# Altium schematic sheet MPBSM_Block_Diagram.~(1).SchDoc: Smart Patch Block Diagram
size 431 x 279 mm; Date: Not shown in title block; ApprovedBy: Not shown in title block; CheckedBy: Not shown in title block; Author: Not shown in title block; CompanyName: Not shown in title block; DrawnBy: Ricky Zepeda; Engineer: Not shown in title block; Organization: Not shown in title block; Address1: Not shown in title block; Address2: Not shown in title block; Address3: Not shown in title block; Address4: Not shown in title block; DocumentNumber: 1; Revision: Use project parameter SCH_Rev; SheetNumber: 1; SheetTotal: 12; PageSetup: Record=PageOptions|CenterHorizontal=True|CenterVertical=True|PrintScale=1.00|XCorrection=1.00|YCorrection=1.00|PrintKind=0|BorderSize=5000000|LeftOffset=0|BottomOffset=0|Orientation=2|PaperLength=1000|PaperWidth=1000|Scale=100|PaperSource=15|PrintQuality=600|MediaType=1|DitherType=10|PaperKind=Letter|PrintScaleMode=1
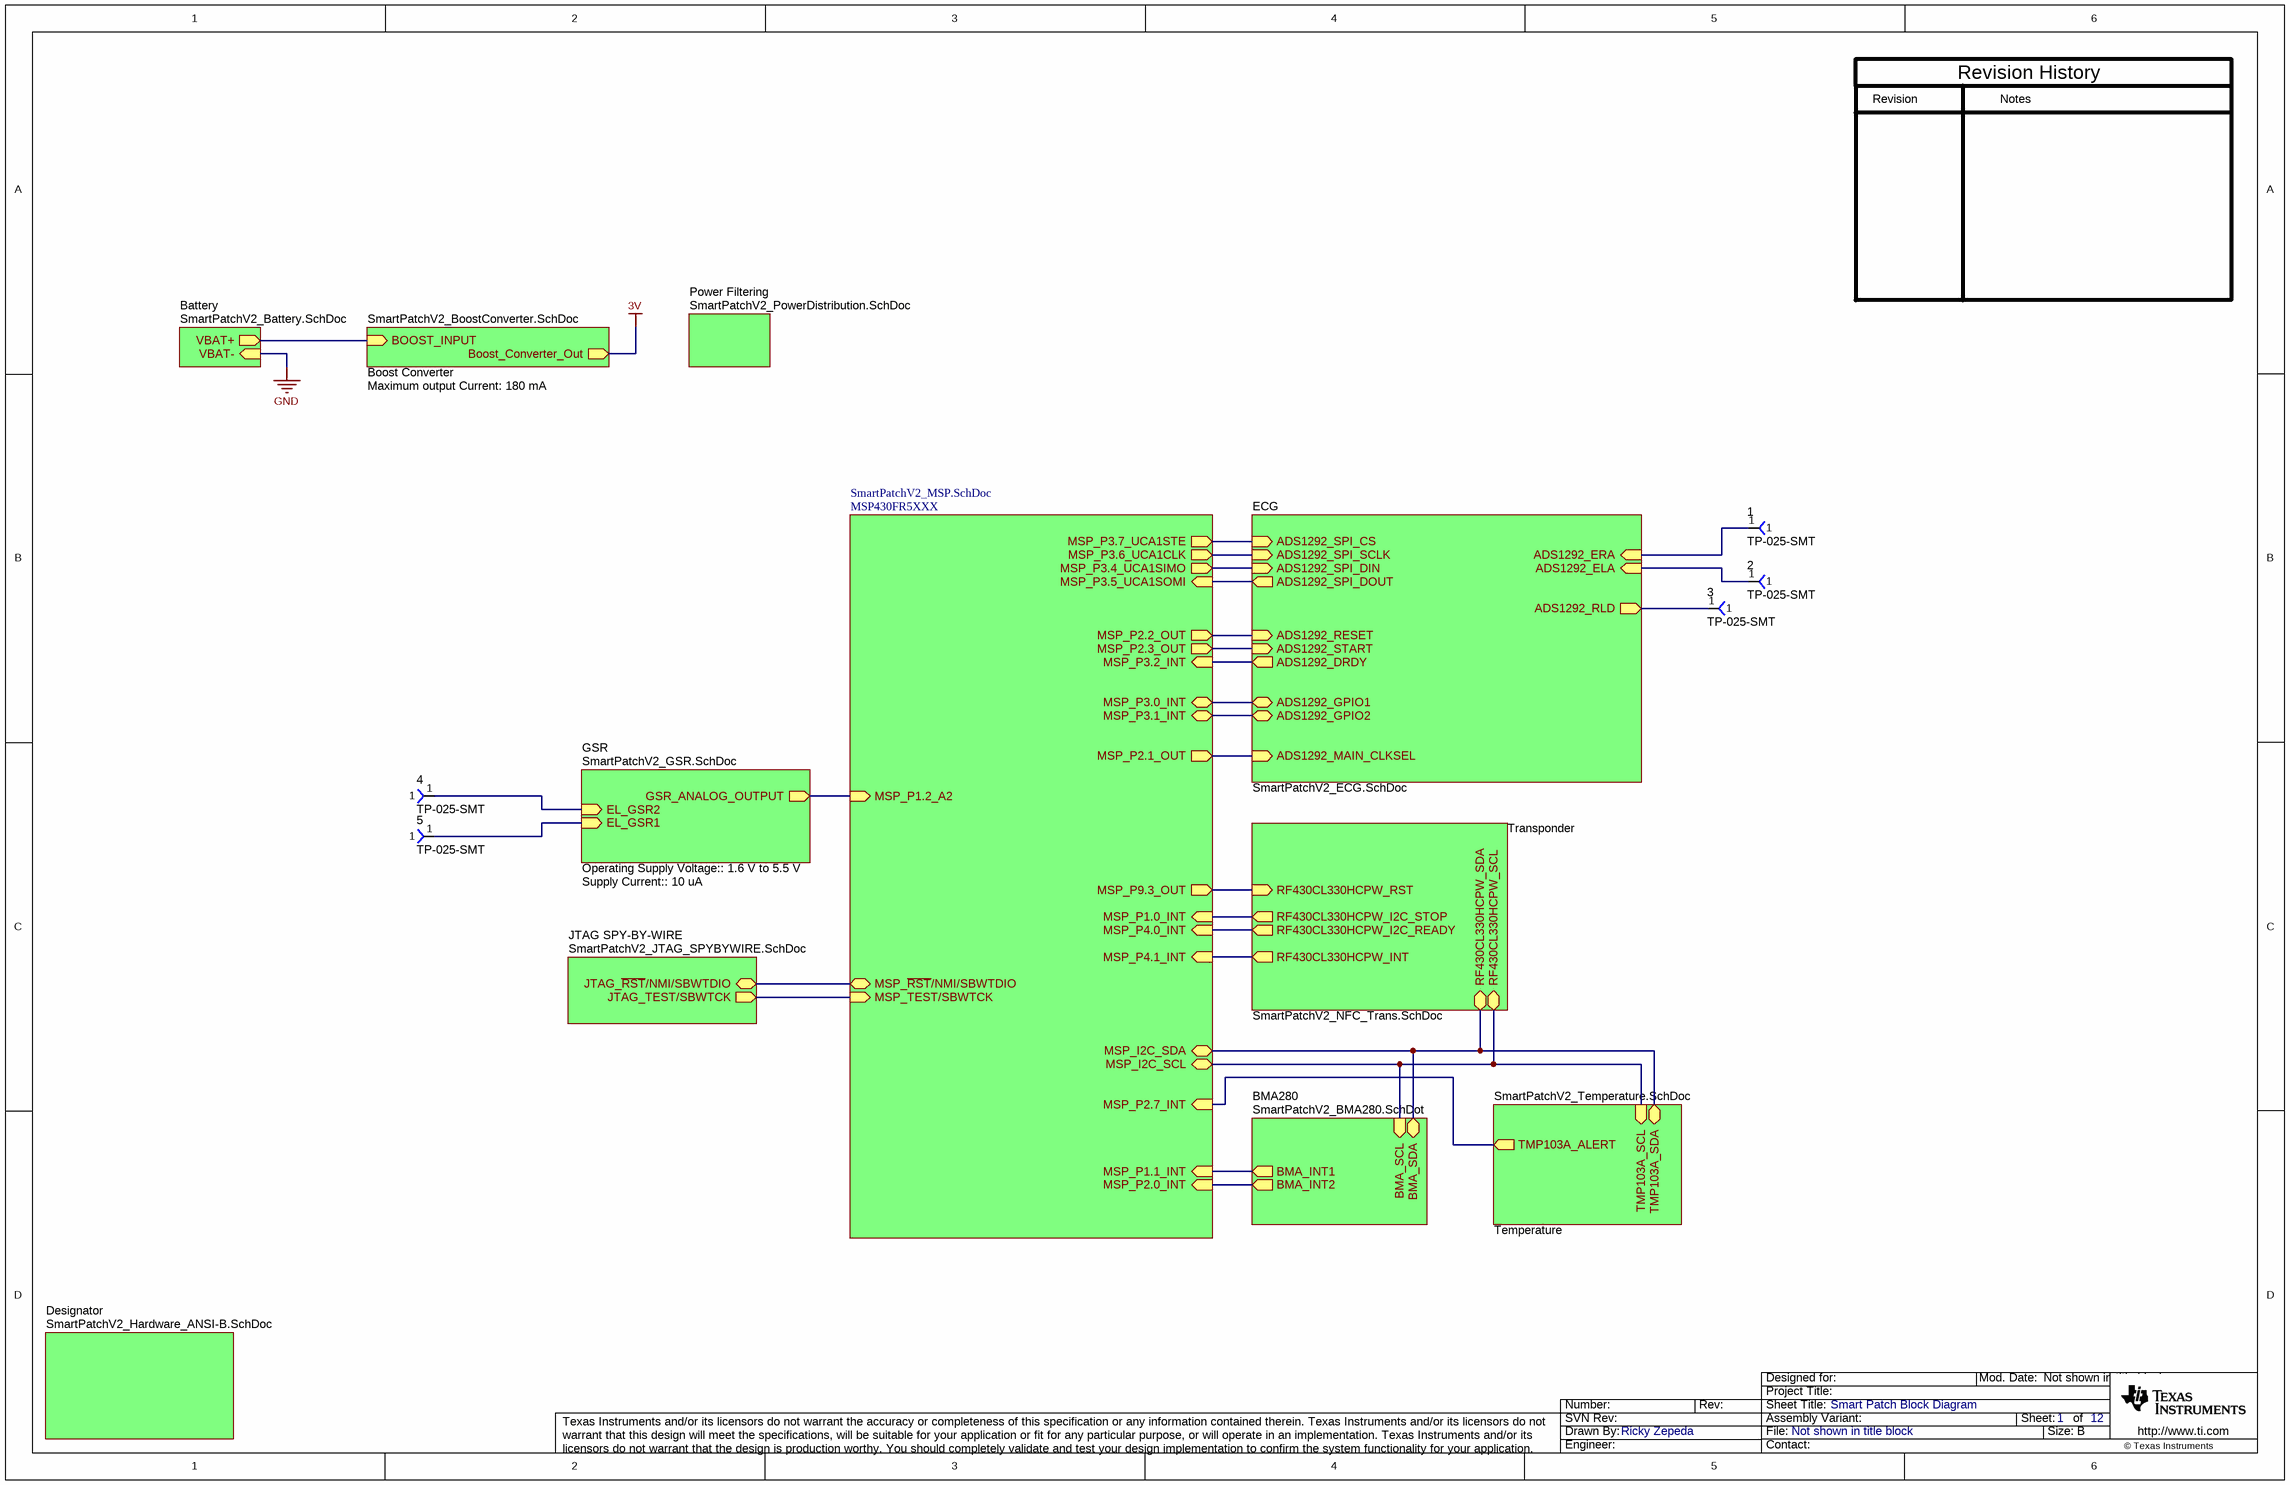
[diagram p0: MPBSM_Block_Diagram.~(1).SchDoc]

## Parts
1  TP-025-SMT  [TP_25MIL-SMT]
2  TP-025-SMT  [TP_25MIL-SMT]
3  TP-025-SMT  [TP_25MIL-SMT]
4  TP-025-SMT  [TP_25MIL-SMT]
5  TP-025-SMT  [TP_25MIL-SMT]

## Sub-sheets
Battery = SmartPatchV2_Battery.SchDoc: VBAT- (in), VBAT+ (out)
BMA280 = SmartPatchV2_BMA280.SchDot: BMA_INT1 (out), BMA_INT2 (out), BMA_SDA (bidir), BMA_SCL (in)
Boost Converter = SmartPatchV2_BoostConverter.SchDoc: BOOST_INPUT (in), Boost_Converter_Out (out)  | Maximum output Current: 180 mA
Designator = SmartPatchV2_Hardware_ANSI-B.SchDoc: no entries
ECG = SmartPatchV2_ECG.SchDoc: ADS1292_START (in), ADS1292_RESET (in), ADS1292_DRDY (out), ADS1292_SPI_CS (in), ADS1292_SPI_DIN (in), ADS1292_SPI_SCLK (in), ADS1292_SPI_DOUT (out), ADS1292_MAIN_CLKSEL (in), ADS1292_ERA (in), ADS1292_ELA (in), ADS1292_GPIO1 (bidir), ADS1292_GPIO2 (bidir), ADS1292_RLD (out)
GSR = SmartPatchV2_GSR.SchDoc: GSR_ANALOG_OUTPUT (out), EL_GSR2 (in), EL_GSR1 (in)  | Operating Supply Voltage:: 1.6 V to 5.5 V; Supply Current:: 10 uA
JTAG SPY-BY-WIRE = SmartPatchV2_JTAG_SPYBYWIRE.SchDoc: JTAG_~{RST}/NMI/SBWTDIO (bidir), JTAG_TEST/SBWTCK (out)
MSP430FR5XXX = SmartPatchV2_MSP.SchDoc: MSP_TEST/SBWTCK (in), MSP_~{RST}/NMI/SBWTDIO (bidir), MSP_I2C_SDA (bidir), MSP_I2C_SCL (bidir), MSP_P1.2_A2 (in), MSP_P2.0_INT (in), MSP_P4.0_INT (in), MSP_P4.1_INT (in), MSP_P2.7_INT (in), MSP_P9.3_OUT (out), MSP_P2.2_OUT (out), MSP_P2.3_OUT (out), MSP_P1.0_INT (in), MSP_P2.1_OUT (out), MSP_P3.0_INT (bidir), MSP_P3.1_INT (bidir), MSP_P3.2_INT (in), MSP_P3.4_UCA1SIMO (out), MSP_P3.5_UCA1SOMI (in), MSP_P3.6_UCA1CLK (out), MSP_P3.7_UCA1STE (out), MSP_P1.1_INT (in)
Power Filtering = SmartPatchV2_PowerDistribution.SchDoc: no entries
Temperature = SmartPatchV2_Temperature.SchDoc: TMP103A_SCL (in), TMP103A_SDA (bidir), TMP103A_ALERT (out)
Transponder = SmartPatchV2_NFC_Trans.SchDoc: RF430CL330HCPW_RST (in), RF430CL330HCPW_SCL (bidir), RF430CL330HCPW_SDA (bidir), RF430CL330HCPW_I2C_STOP (out), RF430CL330HCPW_I2C_READY (out), RF430CL330HCPW_INT (out)

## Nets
Net1_1: 1.1 ; sheet ECG/ADS1292_ERA
Net2_1: 2.1 ; sheet ECG/ADS1292_ELA
Net3_1: 3.1 ; sheet ECG/ADS1292_RLD
Net4_1: 4.1 ; sheet GSR/EL_GSR2
Net5_1: 5.1 ; sheet GSR/EL_GSR1
(unnamed): sheet MSP430FR5XXX/MSP_TEST/SBWTCK, sheet JTAG SPY-BY-WIRE/JTAG_TEST/SBWTCK
(unnamed): sheet MSP430FR5XXX/MSP_~{RST}/NMI/SBWTDIO, sheet JTAG SPY-BY-WIRE/JTAG_~{RST}/NMI/SBWTDIO  [a separate net that carries the same name]
(unnamed): sheet MSP430FR5XXX/MSP_I2C_SDA, sheet Transponder/RF430CL330HCPW_SDA, sheet BMA280/BMA_SDA, sheet Temperature/TMP103A_SDA  [a separate net that carries the same name]
(unnamed): sheet MSP430FR5XXX/MSP_I2C_SCL, sheet Transponder/RF430CL330HCPW_SCL, sheet BMA280/BMA_SCL, sheet Temperature/TMP103A_SCL  [a separate net that carries the same name]
(unnamed): sheet MSP430FR5XXX/MSP_P1.2_A2, sheet GSR/GSR_ANALOG_OUTPUT  [a separate net that carries the same name]
(unnamed): sheet MSP430FR5XXX/MSP_P2.0_INT, sheet BMA280/BMA_INT2  [a separate net that carries the same name]
(unnamed): sheet MSP430FR5XXX/MSP_P4.0_INT, sheet Transponder/RF430CL330HCPW_I2C_READY  [a separate net that carries the same name]
(unnamed): sheet MSP430FR5XXX/MSP_P4.1_INT, sheet Transponder/RF430CL330HCPW_INT  [a separate net that carries the same name]
(unnamed): sheet MSP430FR5XXX/MSP_P2.7_INT, sheet Temperature/TMP103A_ALERT  [a separate net that carries the same name]
(unnamed): sheet MSP430FR5XXX/MSP_P9.3_OUT, sheet Transponder/RF430CL330HCPW_RST  [a separate net that carries the same name]
(unnamed): sheet MSP430FR5XXX/MSP_P2.2_OUT, sheet ECG/ADS1292_RESET  [a separate net that carries the same name]
(unnamed): sheet MSP430FR5XXX/MSP_P2.3_OUT, sheet ECG/ADS1292_START  [a separate net that carries the same name]
(unnamed): sheet MSP430FR5XXX/MSP_P1.0_INT, sheet Transponder/RF430CL330HCPW_I2C_STOP  [a separate net that carries the same name]
(unnamed): sheet MSP430FR5XXX/MSP_P2.1_OUT, sheet ECG/ADS1292_MAIN_CLKSEL  [a separate net that carries the same name]
(unnamed): sheet MSP430FR5XXX/MSP_P3.0_INT, sheet ECG/ADS1292_GPIO1  [a separate net that carries the same name]
(unnamed): sheet MSP430FR5XXX/MSP_P3.1_INT, sheet ECG/ADS1292_GPIO2  [a separate net that carries the same name]
(unnamed): sheet MSP430FR5XXX/MSP_P3.2_INT, sheet ECG/ADS1292_DRDY  [a separate net that carries the same name]
(unnamed): sheet MSP430FR5XXX/MSP_P3.4_UCA1SIMO, sheet ECG/ADS1292_SPI_DIN  [a separate net that carries the same name]
(unnamed): sheet MSP430FR5XXX/MSP_P3.5_UCA1SOMI, sheet ECG/ADS1292_SPI_DOUT  [a separate net that carries the same name]
(unnamed): sheet MSP430FR5XXX/MSP_P3.6_UCA1CLK, sheet ECG/ADS1292_SPI_SCLK  [a separate net that carries the same name]
(unnamed): sheet MSP430FR5XXX/MSP_P3.7_UCA1STE, sheet ECG/ADS1292_SPI_CS  [a separate net that carries the same name]
(unnamed): sheet MSP430FR5XXX/MSP_P1.1_INT, sheet BMA280/BMA_INT1  [a separate net that carries the same name]
(unnamed): sheet Battery/VBAT+, sheet Boost Converter/BOOST_INPUT  [a separate net that carries the same name]

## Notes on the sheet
- Revision
- Notes
- Revision History

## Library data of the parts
1-5 = TP-025-SMT: Test Point, O.025"; Manufacturer: STD; Value: STD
